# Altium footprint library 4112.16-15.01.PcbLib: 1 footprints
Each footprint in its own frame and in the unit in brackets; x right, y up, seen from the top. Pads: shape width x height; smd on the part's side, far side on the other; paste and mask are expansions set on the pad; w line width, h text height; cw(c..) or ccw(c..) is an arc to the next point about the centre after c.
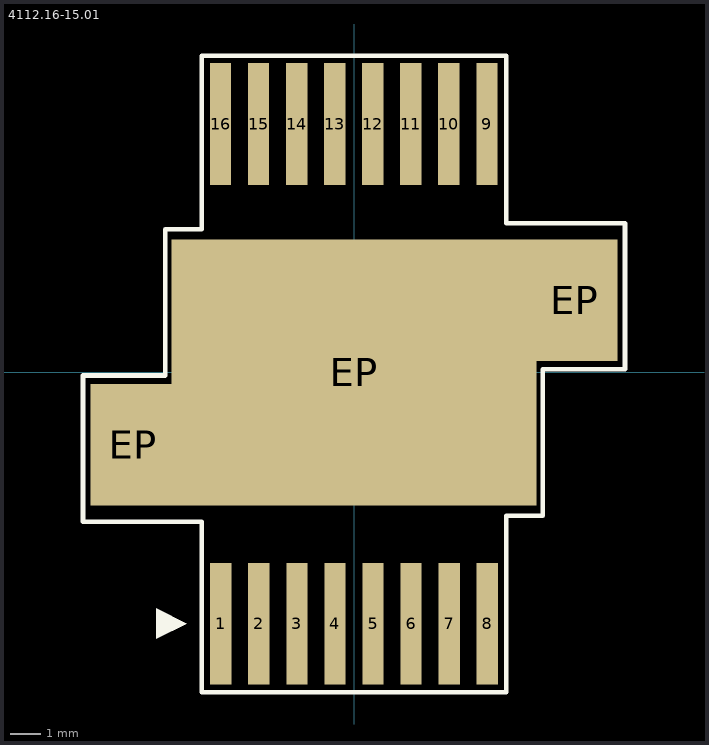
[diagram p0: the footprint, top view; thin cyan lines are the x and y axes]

## 4112.16-15.01 [mm]
pads (19):
  rect 0.7x4 smd: 1(-4.375,-8.25) 2(-3.125,-8.25) 3(-1.875,-8.25) 4(-0.625,-8.25) 5(0.625,-8.25) 6(1.875,-8.25) 7(3.125,-8.25) 8(4.375,-8.25) 9(4.366,8.158) 10(3.116,8.158) 11(1.866,8.158) 12(0.616,8.158) 13(-0.634,8.158) 14(-1.884,8.158) 15(-3.134,8.158) 16(-4.384,8.158)
  rect 2.8x4 smd: EP(-7.25,-2.375) EP(7.25,2.375)
  rect 12x8.75 smd: EP(0,0)
Top Overlay:
  region: -6.5,-8.75 -5.5,-8.25 -6.5,-7.75
  lines w0.15: -8.9,-4.9 -5,-4.9 -5,-10.5 5,-10.5 5,-4.7 6.2,-4.7 6.2,0.1 8.9,0.1 8.9,4.9 5,4.9 5,10.4 -5,10.4 -5,4.7 -6.2,4.7 -6.2,-0.1 -8.9,-0.1 -8.9,-4.9
3D body "4112.16-15.01.step": height 3.05, standoff 0, extent -8.5,-10.25 8.5,10.25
